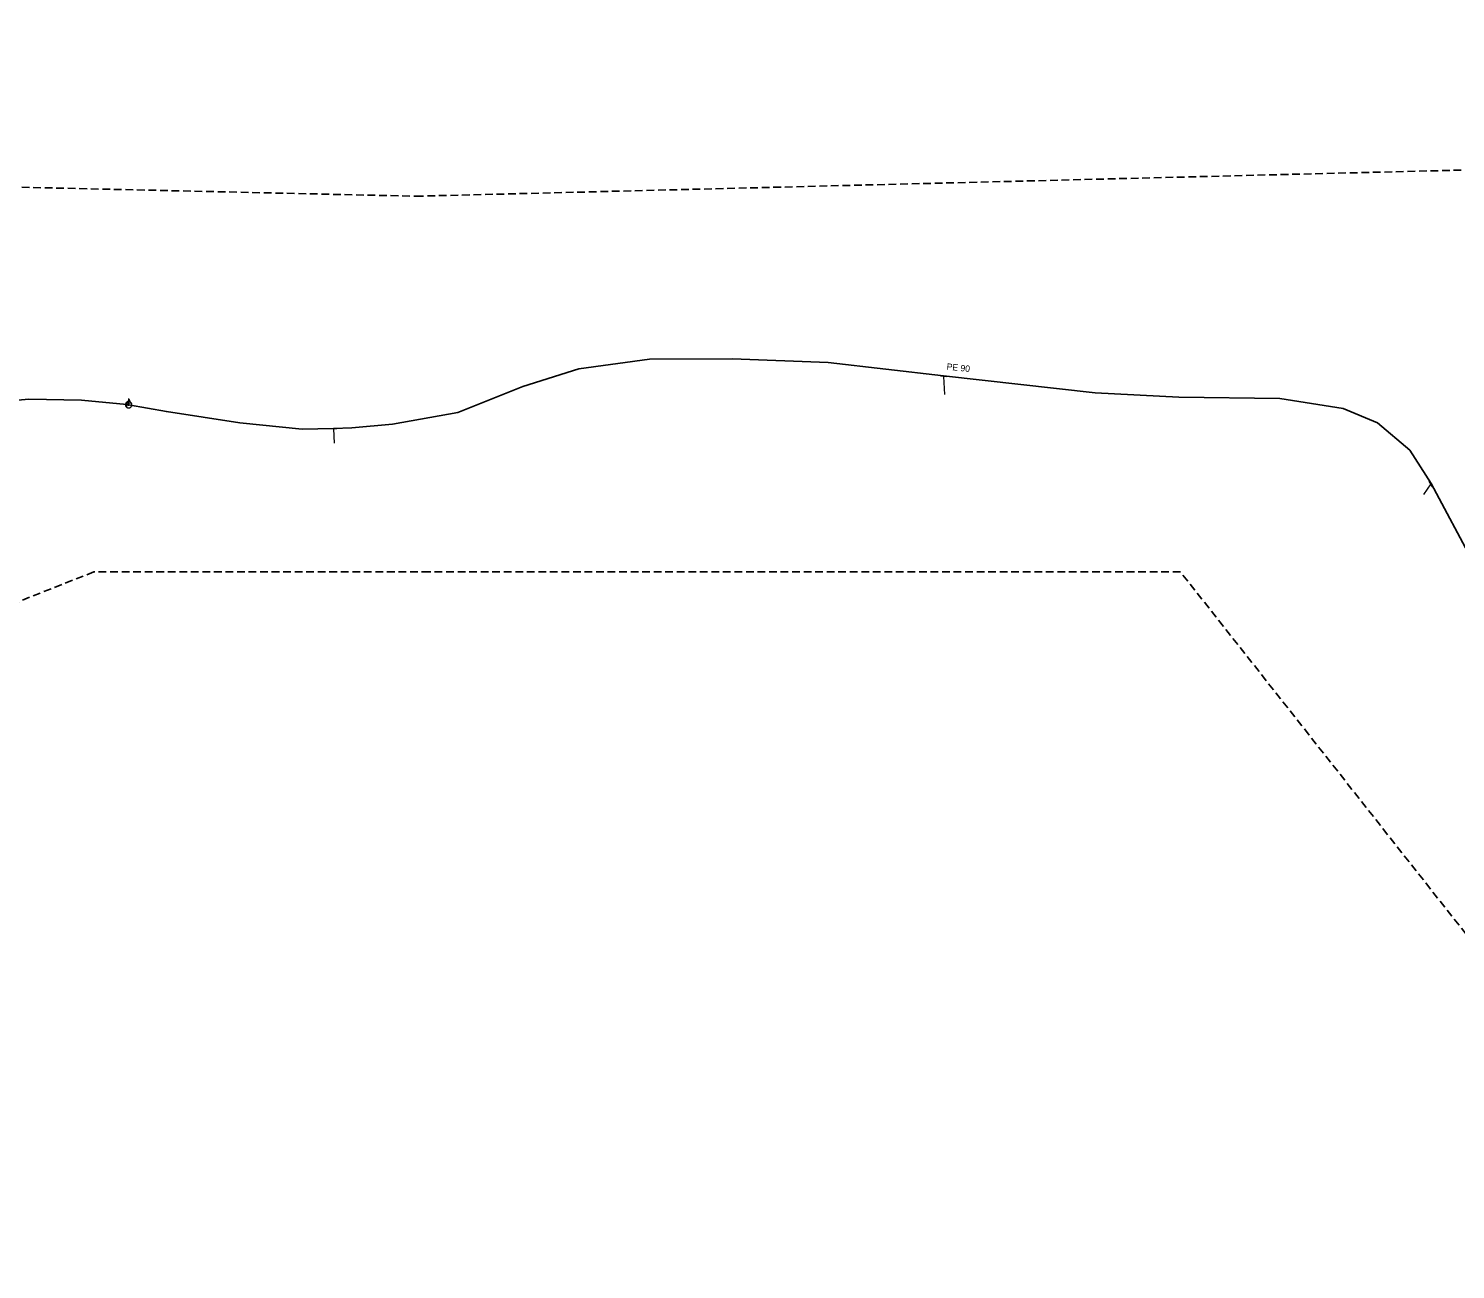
# Model space of a CAD drawing. Extents: x -692311 to -690519, y -971696 to -970899.
# Drawn here: x -691643.1 to -691420.4, y -971286 to -971092.3 of the extents above; entities that cross this region are included whole.
import ezdxf

# ---------------------------------------------------------------- set-up
doc = ezdxf.new("R2010")
doc.units = 0
doc.header["$LTSCALE"] = 0.4
doc.linetypes.add('MEDIUM_DASHED', pattern=[4.5, 3, -1.5])
for name, color, linetype, lineweight in [('1', 7, 'MEDIUM_DASHED', 25), ('13', 7, 'Continuous', 13), ('14', 7, 'Continuous', 13), ('17', 7, 'Continuous', 25), ('34', 7, 'Continuous', 13), ('47', 7, 'Continuous', 13), ('9', 7, 'Continuous', 13)]:
    doc.layers.add(name, color=color, linetype=linetype, lineweight=lineweight)

msp = doc.modelspace()

# ---------------------------------------------------------------- linework, layer by layer
at = {"layer": '1'}
msp.add_lwpolyline([(-691377.453, -971285.953), (-691463.283, -971177.096), (-691580.514, -971177.096), (-691632.849, -971177.096), (-691781.481, -971235.711), (-691971.982, -971202.217), (-692089.213, -971128.947), (-692311.114, -970974.035), (-692304.834, -970898.672), (-692166.669, -970971.942), (-691976.169, -971133.134), (-691904.993, -971149.882), (-691798.229, -971170.816), (-691674.718, -971116.387), (-691582.607, -971118.48), (-691415.135, -971114.294)], dxfattribs=at)
at = {"layer": '13'}
for p, q in [((-691500.261, -971146.615), (-691500.122, -971149.427)), ((-691595.437, -971154.785), (-691595.351, -971156.997)), ((-691424.229, -971163.376), (-691425.37, -971165))]:
    msp.add_line(p, q, dxfattribs=at)
at = {"layer": '14'}
for p, q in [((-691500.25, -971146.52), (-691500.261, -971146.615)), ((-691595.44, -971154.699), (-691595.437, -971154.785)), ((-691424.149, -971163.329), (-691424.229, -971163.376))]:
    msp.add_line(p, q, dxfattribs=at)
msp.add_lwpolyline([(-691627.697, -971150.974), (-691627.43, -971151.02), (-691627.42, -971150.75), (-691627.359, -971150.379)], dxfattribs=at)
at = {"layer": '17'}
for points in [[(-691627.43, -971151.02), (-691621.53, -971152.079), (-691610.07, -971153.859), (-691600.359, -971154.85), (-691595.44, -971154.699), (-691592.59, -971154.609), (-691586.26, -971154.059), (-691576.059, -971152.25), (-691565.899, -971148.18), (-691557.16, -971145.42), (-691546.16, -971143.899), (-691533.18, -971143.87), (-691518.289, -971144.44), (-691500.25, -971146.52), (-691476.579, -971149.16), (-691463.539, -971149.82), (-691447.77, -971150.05), (-691437.879, -971151.59), (-691432.559, -971153.829), (-691427.489, -971158.12), (-691424.149, -971163.329), (-691417.539, -971175.69)], [(-691869.94, -971185.68), (-691853.46, -971190.239), (-691834.84, -971196.649), (-691820.539, -971201.39), (-691811.559, -971203.18), (-691801.644, -971203.824), (-691796.809, -971203.39), (-691789.239, -971202.23), (-691782.879, -971200.84), (-691771.949, -971197.84), (-691763.02, -971194.6), (-691749.03, -971189.17), (-691732.26, -971182.449), (-691706.6, -971172.6), (-691682.829, -971163.359), (-691662.34, -971154.59), (-691650.92, -971150.859), (-691643, -971150.149), (-691634.809, -971150.309), (-691627.697, -971150.974)]]:
    msp.add_lwpolyline(points, dxfattribs=at)
at = {"layer": '34'}
for p, q in [((-691499.764, -971146.671), (-691500.757, -971146.557)), ((-691627.919, -971150.731), (-691626.92, -971150.769)), ((-691627.651, -971150.476), (-691627.743, -971151.471)), ((-691594.937, -971154.769), (-691595.936, -971154.799)), ((-691423.975, -971163.806), (-691424.481, -971162.944))]:
    msp.add_line(p, q, dxfattribs=at)
at = {"layer": '47'}
for points in [[(-691626.937, -971151.108), (-691626.931, -971151.056), (-691626.93, -971151.004), (-691626.935, -971150.952), (-691626.944, -971150.901), (-691626.959, -971150.85), (-691626.98, -971150.802), (-691627.005, -971150.756), (-691627.035, -971150.713), (-691627.069, -971150.674), (-691627.107, -971150.638), (-691627.149, -971150.606), (-691627.194, -971150.579), (-691627.241, -971150.557), (-691627.29, -971150.54), (-691627.341, -971150.527), (-691627.393, -971150.521), (-691627.445, -971150.52), (-691627.498, -971150.525), (-691627.548, -971150.534), (-691627.599, -971150.549), (-691627.647, -971150.57), (-691627.694, -971150.595), (-691627.737, -971150.625), (-691627.776, -971150.659), (-691627.811, -971150.697), (-691627.843, -971150.739), (-691627.871, -971150.784), (-691627.892, -971150.831), (-691627.909, -971150.88), (-691627.922, -971150.931), (-691627.928, -971150.983), (-691627.929, -971151.035), (-691627.925, -971151.088), (-691627.915, -971151.138), (-691627.9, -971151.189), (-691627.88, -971151.237), (-691627.855, -971151.283), (-691627.825, -971151.326), (-691627.79, -971151.366), (-691627.752, -971151.401), (-691627.71, -971151.433), (-691627.666, -971151.461), (-691627.618, -971151.482), (-691627.569, -971151.499), (-691627.518, -971151.512), (-691627.466, -971151.518), (-691627.414, -971151.519), (-691627.362, -971151.515), (-691627.311, -971151.505), (-691627.26, -971151.49), (-691627.212, -971151.47), (-691627.167, -971151.445), (-691627.124, -971151.415), (-691627.084, -971151.38), (-691627.048, -971151.342), (-691627.016, -971151.3), (-691626.989, -971151.256), (-691626.967, -971151.208), (-691626.95, -971151.159)], [(-691627.349, -971151.034), (-691627.347, -971151.025), (-691627.348, -971151.017), (-691627.348, -971151.009), (-691627.35, -971151), (-691627.352, -971150.992), (-691627.356, -971150.984), (-691627.36, -971150.976), (-691627.365, -971150.969), (-691627.371, -971150.963), (-691627.377, -971150.957), (-691627.384, -971150.952), (-691627.391, -971150.947), (-691627.399, -971150.944), (-691627.406, -971150.94), (-691627.415, -971150.939), (-691627.424, -971150.937), (-691627.432, -971150.938), (-691627.44, -971150.938), (-691627.449, -971150.94), (-691627.457, -971150.942), (-691627.465, -971150.946), (-691627.473, -971150.95), (-691627.48, -971150.955), (-691627.487, -971150.96), (-691627.492, -971150.967), (-691627.497, -971150.974), (-691627.502, -971150.981), (-691627.505, -971150.989), (-691627.509, -971150.996), (-691627.51, -971151.005), (-691627.512, -971151.014), (-691627.511, -971151.022), (-691627.511, -971151.03), (-691627.509, -971151.039), (-691627.507, -971151.047), (-691627.504, -971151.055), (-691627.499, -971151.063), (-691627.494, -971151.07), (-691627.489, -971151.077), (-691627.482, -971151.082), (-691627.475, -971151.087), (-691627.468, -971151.092), (-691627.46, -971151.095), (-691627.453, -971151.099), (-691627.444, -971151.1), (-691627.435, -971151.102), (-691627.427, -971151.101), (-691627.419, -971151.101), (-691627.41, -971151.099), (-691627.402, -971151.097), (-691627.394, -971151.094), (-691627.386, -971151.089), (-691627.379, -971151.084), (-691627.373, -971151.078), (-691627.367, -971151.072), (-691627.362, -971151.065), (-691627.357, -971151.058), (-691627.354, -971151.05), (-691627.35, -971151.043)]]:
    msp.add_lwpolyline(points, close=True, dxfattribs=at)
at = {"layer": '9'}
for points in [[(-691627.485, -971150.173), (-691627.532, -971150.158), (-691627.489, -971150.142)], [(-691627.359, -971150.252), (-691627.359, -971150.159), (-691627.532, -971150.158)]]:
    msp.add_lwpolyline(points, dxfattribs=at)
for points in [[(-691627.486, -971150.378), (-691627.485, -971150.391), (-691627.483, -971150.404), (-691627.48, -971150.417), (-691627.475, -971150.429), (-691627.469, -971150.441), (-691627.462, -971150.452), (-691627.454, -971150.462), (-691627.444, -971150.472), (-691627.434, -971150.48), (-691627.423, -971150.487), (-691627.411, -971150.493), (-691627.399, -971150.498), (-691627.386, -971150.501), (-691627.373, -971150.503), (-691627.36, -971150.505), (-691627.347, -971150.505), (-691627.334, -971150.503), (-691627.321, -971150.5), (-691627.309, -971150.495), (-691627.297, -971150.489), (-691627.286, -971150.482), (-691627.276, -971150.474), (-691627.266, -971150.464), (-691627.258, -971150.454), (-691627.251, -971150.443), (-691627.245, -971150.431), (-691627.24, -971150.419), (-691627.237, -971150.406), (-691627.235, -971150.393), (-691627.233, -971150.38), (-691627.234, -971150.367), (-691627.236, -971150.354), (-691627.239, -971150.341), (-691627.244, -971150.329), (-691627.25, -971150.317), (-691627.257, -971150.306), (-691627.265, -971150.296), (-691627.275, -971150.286), (-691627.285, -971150.278), (-691627.296, -971150.271), (-691627.308, -971150.265), (-691627.32, -971150.26), (-691627.333, -971150.257), (-691627.346, -971150.255), (-691627.359, -971150.252), (-691627.372, -971150.253), (-691627.385, -971150.255), (-691627.398, -971150.258), (-691627.41, -971150.263), (-691627.422, -971150.269), (-691627.433, -971150.276), (-691627.443, -971150.284), (-691627.453, -971150.294), (-691627.461, -971150.304), (-691627.468, -971150.315), (-691627.474, -971150.327), (-691627.479, -971150.339), (-691627.482, -971150.352), (-691627.484, -971150.365)], [(-691627.466, -971150.378), (-691627.466, -971150.389), (-691627.464, -971150.4), (-691627.461, -971150.411), (-691627.457, -971150.421), (-691627.452, -971150.431), (-691627.446, -971150.44), (-691627.439, -971150.449), (-691627.431, -971150.457), (-691627.422, -971150.464), (-691627.413, -971150.47), (-691627.403, -971150.475), (-691627.393, -971150.479), (-691627.382, -971150.482), (-691627.371, -971150.484), (-691627.36, -971150.485), (-691627.349, -971150.486), (-691627.338, -971150.484), (-691627.327, -971150.481), (-691627.317, -971150.477), (-691627.307, -971150.472), (-691627.298, -971150.466), (-691627.289, -971150.459), (-691627.281, -971150.451), (-691627.274, -971150.442), (-691627.268, -971150.433), (-691627.263, -971150.423), (-691627.259, -971150.413), (-691627.256, -971150.402), (-691627.254, -971150.391), (-691627.253, -971150.38), (-691627.253, -971150.369), (-691627.255, -971150.358), (-691627.258, -971150.347), (-691627.262, -971150.337), (-691627.267, -971150.327), (-691627.273, -971150.318), (-691627.28, -971150.309), (-691627.288, -971150.301), (-691627.297, -971150.294), (-691627.306, -971150.288), (-691627.316, -971150.283), (-691627.326, -971150.279), (-691627.337, -971150.276), (-691627.348, -971150.274), (-691627.359, -971150.272), (-691627.37, -971150.272), (-691627.381, -971150.274), (-691627.392, -971150.277), (-691627.402, -971150.281), (-691627.412, -971150.286), (-691627.421, -971150.292), (-691627.43, -971150.299), (-691627.438, -971150.307), (-691627.445, -971150.316), (-691627.451, -971150.325), (-691627.456, -971150.335), (-691627.46, -971150.345), (-691627.463, -971150.356), (-691627.465, -971150.367)], [(-691627.447, -971150.378), (-691627.446, -971150.387), (-691627.445, -971150.396), (-691627.442, -971150.405), (-691627.439, -971150.413), (-691627.435, -971150.421), (-691627.43, -971150.429), (-691627.424, -971150.436), (-691627.418, -971150.442), (-691627.411, -971150.448), (-691627.403, -971150.453), (-691627.395, -971150.457), (-691627.387, -971150.46), (-691627.378, -971150.463), (-691627.369, -971150.464), (-691627.36, -971150.467), (-691627.351, -971150.466), (-691627.342, -971150.465), (-691627.333, -971150.462), (-691627.325, -971150.459), (-691627.317, -971150.455), (-691627.309, -971150.45), (-691627.302, -971150.444), (-691627.296, -971150.438), (-691627.29, -971150.431), (-691627.285, -971150.423), (-691627.281, -971150.415), (-691627.278, -971150.407), (-691627.275, -971150.398), (-691627.274, -971150.389), (-691627.272, -971150.38), (-691627.273, -971150.371), (-691627.274, -971150.362), (-691627.277, -971150.353), (-691627.28, -971150.345), (-691627.284, -971150.337), (-691627.289, -971150.329), (-691627.295, -971150.322), (-691627.301, -971150.316), (-691627.308, -971150.31), (-691627.316, -971150.305), (-691627.324, -971150.301), (-691627.332, -971150.298), (-691627.341, -971150.295), (-691627.35, -971150.294), (-691627.359, -971150.291), (-691627.368, -971150.292), (-691627.377, -971150.293), (-691627.386, -971150.296), (-691627.394, -971150.299), (-691627.402, -971150.303), (-691627.41, -971150.308), (-691627.417, -971150.314), (-691627.423, -971150.32), (-691627.429, -971150.327), (-691627.434, -971150.335), (-691627.438, -971150.343), (-691627.441, -971150.351), (-691627.444, -971150.36), (-691627.445, -971150.369)], [(-691627.427, -971150.378), (-691627.427, -971150.385), (-691627.425, -971150.392), (-691627.424, -971150.399), (-691627.421, -971150.405), (-691627.418, -971150.411), (-691627.414, -971150.417), (-691627.41, -971150.423), (-691627.405, -971150.428), (-691627.399, -971150.432), (-691627.393, -971150.436), (-691627.387, -971150.439), (-691627.381, -971150.442), (-691627.374, -971150.443), (-691627.367, -971150.445), (-691627.36, -971150.446), (-691627.353, -971150.447), (-691627.346, -971150.445), (-691627.339, -971150.444), (-691627.333, -971150.441), (-691627.326, -971150.438), (-691627.321, -971150.434), (-691627.315, -971150.43), (-691627.31, -971150.425), (-691627.306, -971150.419), (-691627.302, -971150.413), (-691627.299, -971150.407), (-691627.296, -971150.401), (-691627.294, -971150.394), (-691627.293, -971150.387), (-691627.292, -971150.38), (-691627.292, -971150.373), (-691627.293, -971150.366), (-691627.295, -971150.359), (-691627.298, -971150.353), (-691627.301, -971150.346), (-691627.305, -971150.341), (-691627.309, -971150.335), (-691627.314, -971150.33), (-691627.32, -971150.326), (-691627.325, -971150.322), (-691627.332, -971150.319), (-691627.338, -971150.316), (-691627.345, -971150.314), (-691627.352, -971150.313), (-691627.359, -971150.311), (-691627.366, -971150.311), (-691627.373, -971150.312), (-691627.38, -971150.314), (-691627.386, -971150.317), (-691627.392, -971150.32), (-691627.398, -971150.324), (-691627.404, -971150.328), (-691627.409, -971150.333), (-691627.413, -971150.339), (-691627.417, -971150.344), (-691627.42, -971150.351), (-691627.423, -971150.357), (-691627.424, -971150.364), (-691627.426, -971150.371)], [(-691627.407, -971150.378), (-691627.407, -971150.383), (-691627.406, -971150.388), (-691627.405, -971150.393), (-691627.403, -971150.397), (-691627.401, -971150.402), (-691627.398, -971150.406), (-691627.395, -971150.409), (-691627.391, -971150.413), (-691627.388, -971150.416), (-691627.384, -971150.419), (-691627.379, -971150.421), (-691627.375, -971150.423), (-691627.37, -971150.424), (-691627.365, -971150.425), (-691627.36, -971150.426), (-691627.355, -971150.427), (-691627.35, -971150.426), (-691627.345, -971150.425), (-691627.341, -971150.423), (-691627.336, -971150.421), (-691627.332, -971150.418), (-691627.328, -971150.415), (-691627.325, -971150.411), (-691627.322, -971150.408), (-691627.319, -971150.404), (-691627.317, -971150.399), (-691627.315, -971150.395), (-691627.314, -971150.39), (-691627.313, -971150.385), (-691627.312, -971150.38), (-691627.312, -971150.375), (-691627.313, -971150.37), (-691627.314, -971150.365), (-691627.316, -971150.361), (-691627.318, -971150.356), (-691627.321, -971150.352), (-691627.324, -971150.348), (-691627.327, -971150.345), (-691627.331, -971150.342), (-691627.335, -971150.339), (-691627.34, -971150.337), (-691627.344, -971150.335), (-691627.349, -971150.334), (-691627.354, -971150.333), (-691627.359, -971150.331), (-691627.364, -971150.331), (-691627.369, -971150.332), (-691627.374, -971150.333), (-691627.378, -971150.335), (-691627.383, -971150.337), (-691627.387, -971150.34), (-691627.39, -971150.343), (-691627.394, -971150.346), (-691627.397, -971150.35), (-691627.4, -971150.354), (-691627.402, -971150.359), (-691627.404, -971150.363), (-691627.405, -971150.368), (-691627.406, -971150.373)], [(-691627.387, -971150.378), (-691627.387, -971150.381), (-691627.387, -971150.384), (-691627.386, -971150.386), (-691627.385, -971150.389), (-691627.384, -971150.392), (-691627.382, -971150.394), (-691627.38, -971150.396), (-691627.378, -971150.398), (-691627.376, -971150.4), (-691627.374, -971150.402), (-691627.371, -971150.403), (-691627.368, -971150.404), (-691627.366, -971150.405), (-691627.363, -971150.405), (-691627.36, -971150.405), (-691627.357, -971150.407), (-691627.354, -971150.407), (-691627.351, -971150.406), (-691627.349, -971150.405), (-691627.346, -971150.404), (-691627.344, -971150.402), (-691627.341, -971150.4), (-691627.339, -971150.398), (-691627.338, -971150.396), (-691627.336, -971150.394), (-691627.335, -971150.391), (-691627.334, -971150.388), (-691627.333, -971150.386), (-691627.333, -971150.383), (-691627.331, -971150.38), (-691627.332, -971150.377), (-691627.332, -971150.374), (-691627.333, -971150.371), (-691627.334, -971150.369), (-691627.335, -971150.366), (-691627.337, -971150.364), (-691627.338, -971150.361), (-691627.34, -971150.359), (-691627.343, -971150.358), (-691627.345, -971150.356), (-691627.348, -971150.355), (-691627.35, -971150.354), (-691627.353, -971150.353), (-691627.356, -971150.353), (-691627.359, -971150.35), (-691627.362, -971150.351), (-691627.365, -971150.351), (-691627.367, -971150.352), (-691627.37, -971150.353), (-691627.373, -971150.354), (-691627.375, -971150.356), (-691627.377, -971150.357), (-691627.379, -971150.359), (-691627.381, -971150.362), (-691627.383, -971150.364), (-691627.384, -971150.367), (-691627.385, -971150.369), (-691627.386, -971150.372), (-691627.386, -971150.375)], [(-691627.368, -971150.378), (-691627.368, -971150.379), (-691627.368, -971150.38), (-691627.367, -971150.38), (-691627.367, -971150.381), (-691627.367, -971150.382), (-691627.366, -971150.383), (-691627.366, -971150.383), (-691627.365, -971150.384), (-691627.365, -971150.384), (-691627.364, -971150.385), (-691627.363, -971150.385), (-691627.362, -971150.385), (-691627.362, -971150.386), (-691627.361, -971150.386), (-691627.36, -971150.387), (-691627.359, -971150.387), (-691627.358, -971150.388), (-691627.358, -971150.387), (-691627.357, -971150.387), (-691627.356, -971150.387), (-691627.355, -971150.386), (-691627.355, -971150.386), (-691627.354, -971150.385), (-691627.354, -971150.385), (-691627.353, -971150.384), (-691627.353, -971150.383), (-691627.352, -971150.382), (-691627.352, -971150.382), (-691627.352, -971150.381), (-691627.351, -971150.38), (-691627.351, -971150.379), (-691627.351, -971150.378), (-691627.351, -971150.378), (-691627.352, -971150.377), (-691627.352, -971150.376), (-691627.353, -971150.375), (-691627.353, -971150.375), (-691627.354, -971150.374), (-691627.354, -971150.374), (-691627.355, -971150.373), (-691627.356, -971150.373), (-691627.357, -971150.372), (-691627.357, -971150.372), (-691627.358, -971150.372), (-691627.359, -971150.37), (-691627.36, -971150.37), (-691627.361, -971150.37), (-691627.361, -971150.37), (-691627.362, -971150.371), (-691627.363, -971150.371), (-691627.364, -971150.372), (-691627.364, -971150.372), (-691627.365, -971150.373), (-691627.365, -971150.373), (-691627.366, -971150.374), (-691627.366, -971150.375), (-691627.366, -971150.376), (-691627.367, -971150.376), (-691627.367, -971150.377)]]:
    msp.add_lwpolyline(points, close=True, dxfattribs=at)

# ---------------------------------------------------------------- texts
at = {"layer": '1'}
msp.add_text('PE 90 ', height=1, rotation=354, dxfattribs=at).set_placement((-691499.808, -971145.539))

doc.saveas('drawing.dxf')
